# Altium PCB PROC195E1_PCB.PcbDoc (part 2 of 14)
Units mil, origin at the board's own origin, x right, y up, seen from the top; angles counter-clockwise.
Board outline 3110.24 x 2500 mil, 10 copper layers (Top Layer, L02_GND1, L03_SIG1, L04_GND2, L05_PWR1, L06_PWR2, L07_GND3, L08_SIG2, L09_GND4, Bottom Layer), stack 66.407 mil thick; 571 components, 538 nets, 6726 pads, 1286 vias.
Unrouted connection lines stored in the file: 4.
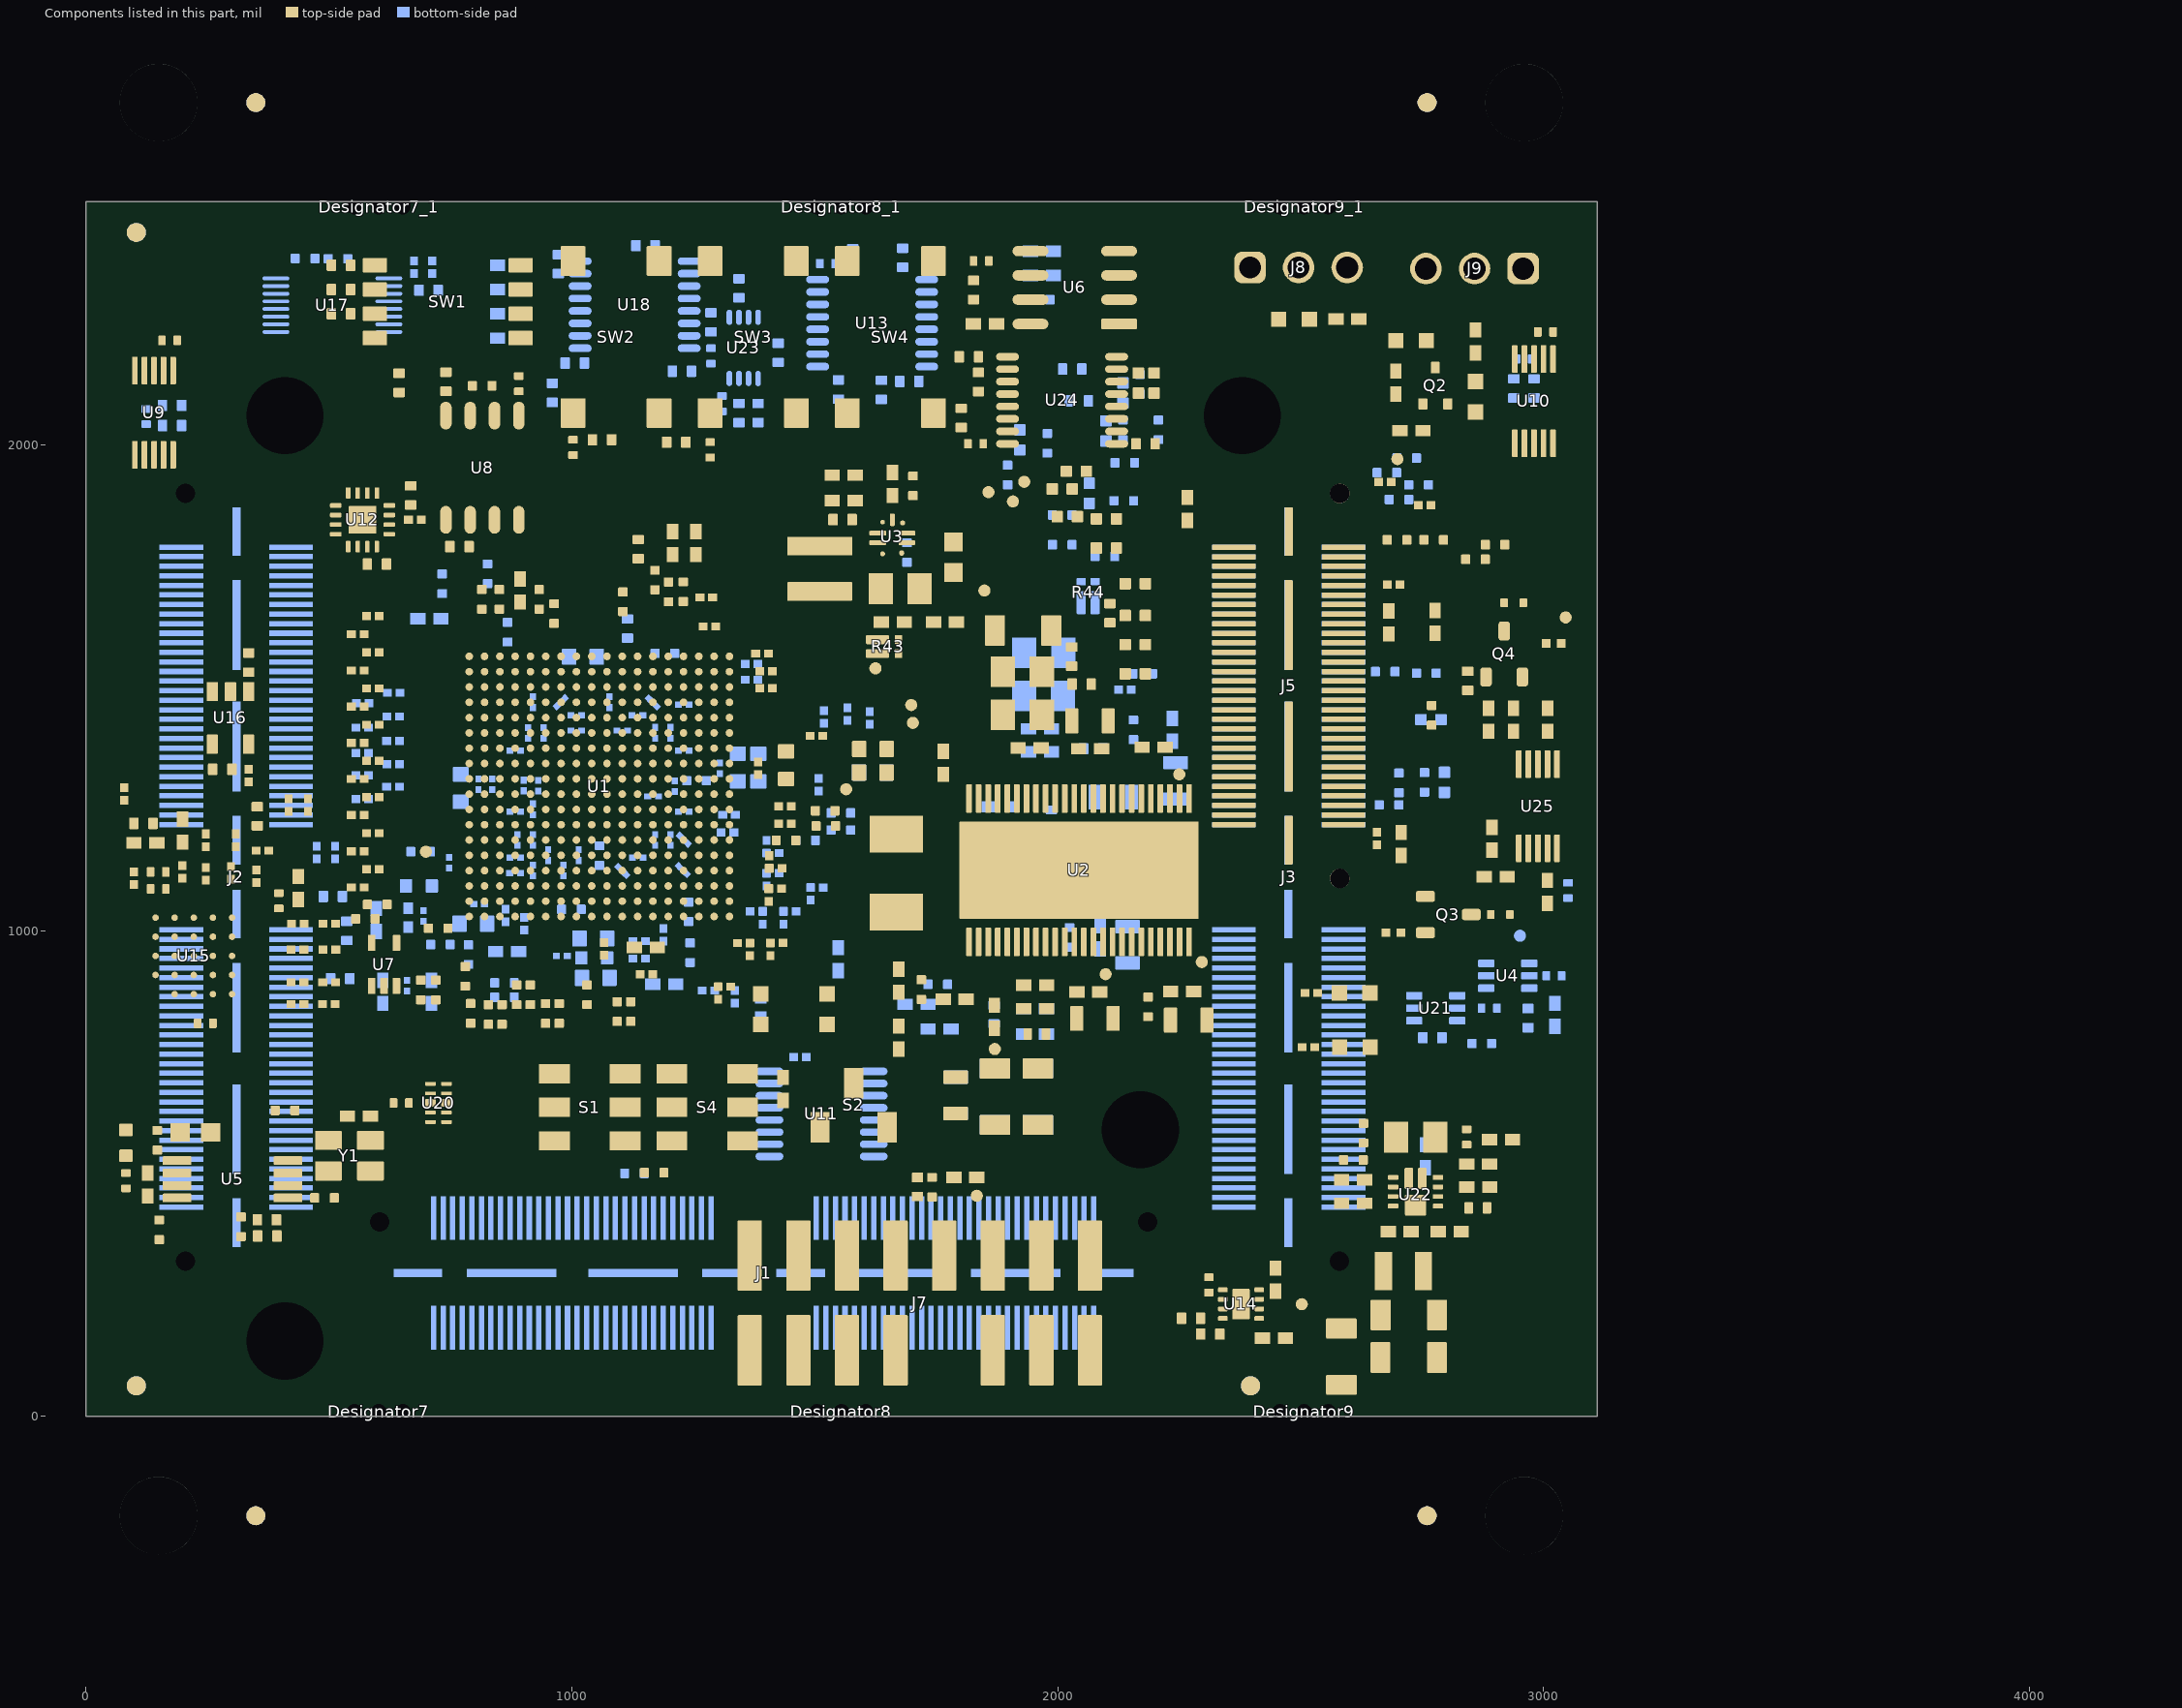
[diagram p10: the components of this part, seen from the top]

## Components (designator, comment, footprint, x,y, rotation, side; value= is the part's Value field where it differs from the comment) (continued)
R185 "RC0402JR-0710KL" FP-RC0402JR-0710KL_0402-MFG 508.58,1070.27 r0 bottom value=10k
R186 "RC0201FR-0722RL" 0201 350.94,1111.7 r90 top value=22.0
R187 "RC0201FR-0722RL" 0201 435.81,893.76 r0 top value=22.0
R188 "ERJ-2GE0R00X" FP-ERJ-2GE0R00X_0402-MFG 2608.6,527.84 r0 top value=0
R189 "RC0201FR-0722RL" 0201 199,1120.7 r90 top value=22.0
R190 "CRCW04021M05FKED" 0402 2756.8,535.51 r90 bottom value=1.05Meg
R191 "RC0201FR-0722RL" 0201 247.18,1116.75 r90 top value=22.0
R192 "CRCW040223K7FKED" 0402 2865.28,519.48 r180 top value=23.7k
R193 "RC0201FR-0722RL" 0201 298.96,1118.7 r90 top value=22.0
R194 "CRCW0402174KFKED" 0402 2607.99,487.06 r0 top value=174k
R195 "RC0201FR-0722RL" 0201 436.67,1013.96 r0 top value=22.0
R196 "RC0201FR-0722RL" 0201 435.81,960.62 r0 top value=22.0
R197 "RC0201FR-0722RL" 0201 435.81,848.86 r0 top value=22.0
R198 "RC0201FR-0722RL" 0201 99.13,1107.76 r90 top value=22.0
R199 "ERJ-1GN0R00C" 0201 79.05,1281.4 r90 top value=0
R200 "ERJ-2RKF1001X" 0402 122.75,1180.75 r180 top value=1.00k
R201 "CRCW0402100KJNED" 0402 597.6,1021.92 r90 bottom value=100k
R202 "CRCW04024K70JNED" 0402 1207.93,1797.45 r90 top value=4.7k
R203 "CRCW04024K70JNED" 0402 1255.29,1797.45 r90 top value=4.7k
R204 "ERJ-2GE0R00X" FP-ERJ-2GE0R00X_0402-MFG 826.74,1734.45 r270 bottom value=0
R205 "RC0402JR-0710KL" FP-RC0402JR-0710KL_0402-MFG 335.2,1551.63 r90 top value=10k
R206 "RC0402JR-0710KL" FP-RC0402JR-0710KL_0402-MFG 281.06,1332.07 r0 top value=10k
R207 "ERJ-2GE0R00X" FP-ERJ-2GE0R00X_0402-MFG 733.39,1713.85 r270 bottom value=0
R208 "ERJ-2GE0R00X" FP-ERJ-2GE0R00X_0402-MFG 933.1,1681.87 r270 top value=0
R209 "CRCW0402118KFKED" 0402 2865.56,472.3 r180 top value=118k
R210 "ERJ-2GE0R00X" FP-ERJ-2GE0R00X_0402-MFG 151.15,384.1 r270 top value=0
R211 "ERJ-2GE0R00X" FP-ERJ-2GE0R00X_0402-MFG 1105.33,1676.87 r270 top value=0
R212 "ERJ-2GE0R00X" FP-ERJ-2GE0R00X_0402-MFG 963.78,1652.65 r270 top value=0
R213 "ERJ-2GE0R00X" FP-ERJ-2GE0R00X_0402-MFG 147.24,568.51 r90 top value=0
R214 "ERJ-2GE0R00X" FP-ERJ-2GE0R00X_0402-MFG 1169.64,501.69 r180 top value=0
R215 "ERJ-2GE0R00X" FP-ERJ-2GE0R00X_0402-MFG 1129.23,500.3 r0 bottom value=0
R216 "CRCW0402100RFKED" 0402 2681.28,1634.07 r90 top value=100
R217 "ERJ-2GE0R00X" FP-ERJ-2GE0R00X_0402-MFG 1171.31,1721.49 r270 top value=0
R218 "ERJ-2RKF1001X" 0402 871.25,2369.54 r180 bottom value=1.00k
R219 "ERJ-2RKF1001X" 0402 871.25,2319.54 r180 bottom value=1.00k
R220 "ERJ-2RKF1001X" 0402 871.25,2269.54 r180 bottom value=1.00k
R221 "ERJ-2RKF1001X" 0402 871.25,2219.54 r180 bottom value=1.00k
R222 "RC0402JR-0710KL" FP-RC0402JR-0710KL_0402-MFG 705.41,2317.95 r0 bottom value=10k
R223 "RC0402JR-0710KL" FP-RC0402JR-0710KL_0402-MFG 352.91,1235.31 r90 top value=10k
R224 "RC0402JR-0710KL" FP-RC0402JR-0710KL_0402-MFG 523.69,901 r0 bottom value=10k
R225 "RC0402JR-0710KL" FP-RC0402JR-0710KL_0402-MFG 1136.94,1785.19 r90 top value=10k
R226 "RC0402JR-0710KL" FP-RC0402JR-0710KL_0402-MFG 1114.68,1621.77 r90 bottom value=10k
R227 "RC0402JR-0710KL" FP-RC0402JR-0710KL_0402-MFG 644.79,2127.36 r90 top value=10k
R228 "RC0402JR-0710KL" FP-RC0402JR-0710KL_0402-MFG 525.19,2269.54 r0 top value=10k
R229 "RC0402JR-0710KL" FP-RC0402JR-0710KL_0402-MFG 525.19,2319.54 r0 top value=10k
R230 "RC0402JR-0710KL" FP-RC0402JR-0710KL_0402-MFG 525.19,2369.54 r0 top value=10k
R231 "ERJ-2GE0R00X" FP-ERJ-2GE0R00X_0402-MFG 451.38,2383.37 r0 bottom value=0
R232 "ERJ-2GE0R00X" FP-ERJ-2GE0R00X_0402-MFG 519.14,2382.89 r180 bottom value=0
R233 "ERJ-2GEJ152X" FP-ERJ-2GEJ152X_0402-MFG 1553.88,1206.89 r180 bottom value=1.5k
R234 "ERJ-2GEJ152X" FP-ERJ-2GEJ152X_0402-MFG 1481.4,1185.59 r0 bottom value=1.5k
R235 "ERJ-2GE0R00X" FP-ERJ-2GE0R00X_0402-MFG 1441.05,1185.59 r180 top value=0
R236 "ERJ-2GE0R00X" FP-ERJ-2GE0R00X_0402-MFG 1553.88,1242.11 r180 bottom value=0
R237 "ERJ-2GE0R00X" FP-ERJ-2GE0R00X_0402-MFG 729.88,971.43 r0 bottom value=0
R238 "ERJ-1GN0R00C" 0201 1613.18,1437.62 r90 bottom value=0
R239 "ERJ-1GN0R00C" 0201 1335.6,863.52 r90 bottom value=0
R240 "ERJ-2GE0R00X" FP-ERJ-2GE0R00X_0402-MFG 946.13,829.5 r90 top value=0
R241 "ERJ-2GE0R00X" FP-ERJ-2GE0R00X_0402-MFG 974.13,829.5 r90 top value=0
R242 "ERJ-2GE0R00X" FP-ERJ-2GE0R00X_0402-MFG 861.61,862.81 r0 bottom value=0
R243 "ERJ-2GE0R00X" FP-ERJ-2GE0R00X_0402-MFG 861.61,892.26 r0 bottom value=0
R244 "ERJ-2GE0R00X" FP-ERJ-2GE0R00X_0402-MFG 1093.49,833.2 r90 top value=0
R245 "RC0402JR-0710KL" FP-RC0402JR-0710KL_0402-MFG 1062.42,2010.26 r180 top value=10k
R246 "RC0402JR-0710KL" FP-RC0402JR-0710KL_0402-MFG 2771.13,779.4 r0 bottom value=10k
R247 "ERJ-2GE0R00X" FP-ERJ-2GE0R00X_0402-MFG 2872.7,767.51 r180 bottom value=0
R248 "RC0402JR-0710KL" FP-RC0402JR-0710KL_0402-MFG 1344.16,2065.26 r90 bottom value=10k
R249 "CRCW04024K70JNED" 0402 3023.19,826.5 r90 bottom value=4.7k
R250 "RC0402JR-0710KL" FP-RC0402JR-0710KL_0402-MFG 1215.21,2005.26 r0 top value=10k
R251 "RC0402JR-0710KL" FP-RC0402JR-0710KL_0402-MFG 2968,819.85 r270 bottom value=10k
R252 "RC0402JR-0710KL" FP-RC0402JR-0710KL_0402-MFG 1826.89,2318.57 r90 top value=10k
R253 "RC0402JR-0710KL" FP-RC0402JR-0710KL_0402-MFG 1344.16,2322.1 r270 bottom value=10k
R254 "RC0402JR-0710KL" FP-RC0402JR-0710KL_0402-MFG 2043.54,2090.36 r0 bottom value=10k
R255 "RC0402JR-0710KL" FP-RC0402JR-0710KL_0402-MFG 2029.91,2155.79 r0 bottom value=10k
R256 "RC0402JR-0710KL" FP-RC0402JR-0710KL_0402-MFG 1817.2,2181.04 r0 top value=10k
R257 "RC0402JR-0710KL" FP-RC0402JR-0710KL_0402-MFG 1836.89,2129.2 r270 top value=10k
R258 "RC0402JR-0710KL" FP-RC0402JR-0710KL_0402-MFG 2180.98,2002.06 r0 top value=10k
R259 "RC0402JR-0710KL" FP-RC0402JR-0710KL_0402-MFG 1801.56,2055.24 r270 top value=10k
R260 "CRCW04024K70JNED" 0402 2706.82,1178.56 r270 top value=4.7k
R261 "ERJ-1GN0R00C" 0201 1393.15,1026.54 r90 bottom value=0
R262 "ERJ-1GN0R00C" 0201 1401.07,1172.66 r270 bottom value=0
R263 "ERJ-1GN0R00C" 0201 1414.06,1159.67 r180 bottom value=0
R264 "ERJ-1GN0R00C" 0201 1314.34,884.78 r0 top value=0
R265 "ERJ-2RKF1001X" 0402 2727.9,2028.96 r0 top value=1.00k
R266 "CRCW04024K70JNED" 0402 2886.74,1434.06 r90 top value=4.7k
R267 "CRCW04024K70JNED" 0402 2938.15,1433.98 r90 top value=4.7k
R268 "CRCW04024K70JNED" 0402 3008.15,1433.98 r90 top value=4.7k
R269 "ERJ-2RKF1001X" 0402 2893.51,1188.98 r270 top value=1.00k
R270 "ERJ-2RKF1001X" 0402 2901.38,1110.57 r180 top value=1.00k
R271 "AC0402FR-0710KL" 0402 3007.89,1079.84 r90 top value=10.0k
R272 "ERJ-2GE0R00X" FP-ERJ-2GE0R00X_0402-MFG 1121.49,833.2 r90 top value=0
R273 "ERJ-2GE0R00X" FP-ERJ-2GE0R00X_0402-MFG 914.72,867.87 r90 top value=0
R274 "ERJ-2GE0R00X" FP-ERJ-2GE0R00X_0402-MFG 886.72,867.87 r90 top value=0
R275 "ERJ-2GE0R00X" FP-ERJ-2GE0R00X_0402-MFG 828.55,827.38 r90 top value=0
R276 "ERJ-2GE0R00X" FP-ERJ-2GE0R00X_0402-MFG 856.55,827.38 r90 top value=0
R277 "ERJ-2GE0R00X" FP-ERJ-2GE0R00X_0402-MFG 781.1,905.79 r90 top value=0
R278 "ERJ-2GE0R00X" FP-ERJ-2GE0R00X_0402-MFG 791.99,829.72 r90 top value=0
R279 "ERJ-2GEJ221X" RESC1005X40X25LL05T05 2690.99,995.64 r180 top
R280 "ERJ-2GEJ221X" RESC1005X40X25LL05T05 3020.77,1591.21 r0 top
R281 "RC0402JR-0710KL" FP-RC0402JR-0710KL_0402-MFG 2843.82,1514.02 r270 top value=10k
R282 "ERJ-1GN0R00C" 0201 1469.89,739.87 r0 bottom value=0
R283 "ERJ-1GN0R00C" 0201 1301.35,871.79 r270 top value=0
R284 "ERJ-1GN0R00C" 0201 1421.89,974.55 r0 top value=0
R285 "ERJ-1GN0R00C" 0201 1408.9,961.55 r270 top value=0
R286 "ERJ-1GN0R00C" 0201 1353.81,974.18 r180 top value=0
R287 "ERJ-1GN0R00C" 0201 1366.8,961.19 r270 top value=0
R288 "ERJ-1GN0R00C" 0201 1448.66,1039.53 r0 bottom value=0
R289 "ERJ-1GN0R00C" 0201 1435.67,1026.54 r270 bottom value=0
R290 "ERJ-1GN0R00C" 0201 1401.07,1105.07 r270 bottom value=0
R291 "ERJ-1GN0R00C" 0201 1414.06,1118.06 r0 bottom value=0
R292 "ERJ-1GN0R00C" 0201 1405.5,1073.36 r270 top value=0
R293 "ERJ-1GN0R00C" 0201 1418.5,1086.35 r0 top value=0
R294 "ERJ-1GN0R00C" 0201 1406.47,1141.17 r90 top value=0
R295 "ERJ-1GN0R00C" 0201 1419.46,1128.18 r0 top value=0
R296 "ERJ-1GN0R00C" 0201 1491.61,1075.61 r270 bottom value=0
R297 "ERJ-1GN0R00C" 0201 1504.6,1088.61 r0 bottom value=0
R298 "RC0402JR-0710KL" FP-RC0402JR-0710KL_0402-MFG 1637.24,2113.04 r90 bottom value=10k
R299 "RC0402JR-0710KL" FP-RC0402JR-0710KL_0402-MFG 1694.75,2130.44 r180 bottom value=10k
R300 "RC0402JR-0710KL" FP-RC0402JR-0710KL_0402-MFG 1548.89,2113.57 r90 bottom value=10k
R301 "RC0402JR-0710KL" FP-RC0402JR-0710KL_0402-MFG 1424.91,2189.25 r90 bottom value=10k
R302 "RC0402JR-0710KL" FP-RC0402JR-0710KL_0402-MFG 1681.01,2384.85 r90 bottom value=10k
R303 "RC0402JR-0710KL" FP-RC0402JR-0710KL_0402-MFG 1578.39,2383.49 r90 bottom value=10k
R304 "RC0402JR-0710KL" FP-RC0402JR-0710KL_0402-MFG 960.1,2106.8 r90 bottom value=10k
R305 "RC0402JR-0710KL" FP-RC0402JR-0710KL_0402-MFG 1006.32,2168.12 r180 bottom value=10k
R306 "RC0402JR-0710KL" FP-RC0402JR-0710KL_0402-MFG 972.3,2371.88 r270 bottom value=10k
R307 "RC0402JR-0710KL" FP-RC0402JR-0710KL_0402-MFG 1151.82,2409.8 r0 bottom value=10k
R308 "RC0402JR-0710KL" FP-RC0402JR-0710KL_0402-MFG 1286.71,2252.02 r90 bottom value=10k
R309 "RC0402JR-0710KL" FP-RC0402JR-0710KL_0402-MFG 1226.82,2151.47 r0 bottom value=10k
R310 "ERJ-1GN0R00C" 0201 902.53,1013.91 r90 bottom value=0
R311 "ERJ-1GN0R00C" 0201 475.11,1160.36 r90 bottom value=0
R312 "ERJ-1GN0R00C" 0201 513.3,1160.36 r90 bottom value=0
R313 "ERJ-2GE0R00X" FP-ERJ-2GE0R00X_0402-MFG 2773.71,1804.15 r180 top value=0
R314 "ERJ-2GE0R00X" FP-ERJ-2GE0R00X_0402-MFG 2718.22,1972.55 r180 bottom value=0
R315 "ERJ-2GE0R00X" FP-ERJ-2GE0R00X_0402-MFG 2900.15,1794.32 r180 top value=0
R316 "ERJ-2GE0R00X" FP-ERJ-2GE0R00X_0402-MFG 2742.84,1917.46 r180 bottom value=0
S1 "CAS-D20TA" SW_CAS-D20TA 1037.26,636.32 r0 top
S2 "CAS-120TA" SW_CAS-120TA 1580.11,640.8 r90 top
S4 "CAS-D20TA" SW_CAS-D20TA 1278.67,636.33 r0 top
SW1 "416131160804" FP-416131160804_SMT_SW-MFG 744.87,2294.54 r270 top
SW2 "430182050816" FP-430182050816_SMT_SW_6MM2_6MM2-MFG 1091.32,2221.76 r270 top
SW3 "430182050816" FP-430182050816_SMT_SW_6MM2_6MM2-MFG 1373.48,2221.76 r270 top
SW4 "430182050816" FP-430182050816_SMT_SW_6MM2_6MM2-MFG 1655.65,2221.76 r90 top
TP1 "TESTPOINT" TP_25MIL-SMT 699.97,1162.37 r90 top
TP2 "TESTPOINT" TP_25MIL-SMT 2250.34,1321.58 r180 top
TP3 "TESTPOINT" TP_25MIL-SMT 2502.44,230.99 r90 top
TP4 "TESTPOINT" TP_25MIL-SMT 2699.22,1970.52 r90 top
TP5 "TESTPOINT" TP_25MIL-SMT 2296.51,935.35 r90 top
TP6 "TESTPOINT" TP_25MIL-SMT 1870.71,756.2 r90 top
TP7 "TESTPOINT" TP_25MIL-SMT 1833.72,454.17 r90 top
TP8 "TESTPOINT" TP_25MIL-SMT 1849.33,1700.02 r90 top
TP9 "TESTPOINT" TP_25MIL-SMT 2098.78,910.2 r0 top
TP10 "TESTPOINT" TP_25MIL-SMT 3045.37,1644.52 r90 top
TP11 "TESTPOINT" TP_25MIL-SMT 1931.18,1923.68 r0 top
TP12 "TESTPOINT" TP_25MIL-SMT 1907.87,1883.27 r270 top
TP13 "TESTPOINT" TP_25MIL-SMT 1702.27,1427.61 r90 top
TP14 "TESTPOINT" TP_25MIL-SMT 1857.69,1902.47 r180 top
TP15 "TESTPOINT" TP_25MIL-SMT 1698.58,1464.36 r180 top
TP16 "TESTPOINT" TP_25MIL-SMT 1625.09,1539.81 r0 top
TP17 "TESTPOINT" TP_25MIL-SMT 1564.79,1290.88 r90 top
TP18 "TESTPOINT" TP_25MIL-SMT 2951.32,989.35 r0 bottom
U1 "AM261x_ZCZ" ZCZ0324A-MFG 1056.88,1296.69 r0 top locked
U2 "TPS6538600QDCARQ1" DCA0048J-MFG 2044.02,1124.31 r90 top locked
U3 "TPS62903QRYTQ1" RYT0009A-MFG 1659.81,1808.16 r0 top
U4 "SN74LVC1G11DCKR" DCK0006A_N 2926.27,906.96 r0 bottom
U5 "LMK1C1104PWR" PW0008A-MFG 301.97,488.18 r180 top
U6 "CAT24M01WI-GT3" FP-CAT24M01WI-GT3_SOIC8-IPC_C 2035.19,2323.61 r180 top
U7 "SN74LV1T34DCKR" DCK0005A_N 613.98,930.43 r90 top
U8 "TMP411ADR" D0008A_N 816.14,1952.78 r270 top
U9 "INA228AIDGST" DGS0010A-MFG 140.51,2065.98 r90 top
U10 "INA228AIDGST" DGS0010A-MFG 2980.11,2089.59 r90 top
U11 "OPA4350EA/250" DBQ0016A_N 1514.17,622.68 r0 bottom
U12 "TCA6408ARGTR" RGT0016A 569.55,1845.49 r270 top
U13 "SN74CB3Q3257PWR" PW0016A_L 1618.37,2250.46 r180 bottom
U14 "TPS22965DSGT" DSG0008A-MFG 2377.36,231.18 r0 top
U15 "IS25LX256-LHLE" FP-IS25LX256-LHLE_TFBGA24-IPC_C 222.33,947.98 r90 top
U16 "SN74LVC1G08DBVR" DBV0005A_N 297.79,1437.81 r270 top
U17 "SN74AVC4T245DGVR" DGV0016A_N 507.56,2287.31 r180 bottom
U18 "SN74CB3Q3257PWR" PW0016A_L 1129.51,2288.22 r0 bottom
U20 "TMUX1136DQAR" DQA0010A 725.57,645.23 r180 top
U21 "SN74LVC1G11DCKR" DCK0006A_N 2777.91,840.27 r0 bottom
U22 "TPS61089RNRR" RNR0011A 2736.45,462.45 r180 top
U23 "SN74LVC3G17DCUR" DCU0008A_N 1354.01,2199.42 r270 bottom
U24 "SN74CB3Q3257PWR" PW0016A_L 2009.09,2091.63 r180 top
U25 "TMUX154EDGSR" DGS0010A-MFG 2988.2,1256.06 r270 top
Y1 "831055678" FP-831055678_SMT_OSC_3MM2_2MM5-MFG 542.64,536.65 r180 top
ZZ1 "This Assembly Note is for PCB labels only" ASSEMBLYNOTELABEL -337,3585 r0 top
ZZ2 "These assemblies are ESD sensitive, ESD precautions shall be observed." ASSEMBLYNOTE -346.3,3701.23 r0 top
ZZ3 "These assemblies must be clean and free from flux and all contaminants. Use of no clean flux is not acceptable." ASSEMBLYNOTE -347,3790 r0 top
ZZ4 "These assemblies must comply with workmanship standards IPC-A-610 Class 2, unless otherwise specified." ASSEMBLYNOTE -351,3896 r0 top

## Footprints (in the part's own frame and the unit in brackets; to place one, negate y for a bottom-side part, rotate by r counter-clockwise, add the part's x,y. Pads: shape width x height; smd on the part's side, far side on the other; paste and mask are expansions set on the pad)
0201 [mm] "Data from Kemet datasheet CC101_COM dated 7/28/11"
  rect 0.46x0.42 smd mask+0.048: 1(-0.33,0) 2(0.33,0)
  body extent -0.31,-0.16 0.31,0.16, height 0.26
0201L [mm] "Data from Kemet datasheet CC101_COM dated 7/28/11"
  rect 0.36x0.32 smd mask+0.048: 1(-0.28,0) 2(0.28,0)
  body extent -0.31,-0.16 0.31,0.16, height 0.26
0402 [mm] "0402 from SM-752 data"
  rect 0.8x0.6 smd: 1(-0.6,0) 2(0.6,0)
  silkscreen extent -1.22,-0.52 1.22,0.52, body extent -0.55,-0.3 0.55,0.3, height 0.6
0402L [mm] "0402 from SM-752 data"
  rect 0.6x0.5 smd: 1(-0.5,0) 2(0.5,0)
  body extent -0.55,-0.3 0.55,0.3, height 0.6
0603 [mm] "0603 from SM-752 data"
  rect 1x0.95 smd: 1(-0.8,0) 2(0.8,0)
  silkscreen extent -1.52,-0.69 1.52,0.69, body extent -0.87,-0.47 0.87,0.47, height 1
0805_HV [mil] "0805 with 30mil clearance between pads"
  rect 50x63 smd: 1(-40,0) 2(40,0)
  silkscreen extent -74,-40 74,40, body extent -43,-29 43,29, height 57
ASSEMBLYNOTE [mil] "Assembly Note"
ASSEMBLYNOTELABEL [mil] "Assembly Note for PCB Labels"
BRAKE_WAY_HOLES1X3 [mil]
  round 27 hole 32 unplated mask+5.5: ""(-50,49.37) ""(0,49.37) ""(50,49.37)
CE_MARK_5MM [mil] "Minimum text height for CE Mark"
  silkscreen extent -138,-99 138,99
CONN_QSH-060-01-L-D-A [mil] "SAMTEC"
  rect 11x90 smd: 1(-679.23,-112.41) 2(-679.23,113.19) 3(-659.55,-112.41) 4(-659.55,113.19) 5(-639.86,-112.41) 6(-639.86,113.19) 7(-620.18,-112.41) 8(-620.18,113.19) 9(-600.49,-112.41) 10(-600.49,113.19) 11(-580.81,-112.41) 12(-580.81,113.19) 13(-561.12,-112.41) 14(-561.12,113.19) 15(-541.44,-112.41) 16(-541.44,113.19) 17(-521.75,-112.41) 18(-521.75,113.19) 19(-502.07,-112.41) 20(-502.07,113.19) 21(-482.38,-112.41) 22(-482.38,113.19) 23(-462.7,-112.41) 24(-462.7,113.19) 25(-443.01,-112.41) 26(-443.01,113.19) 27(-423.33,-112.41) 28(-423.33,113.19) 29(-403.64,-112.41) 30(-403.64,113.19) 31(-383.96,-112.41) 32(-383.96,113.19) 33(-364.27,-112.41) 34(-364.27,113.19) 35(-344.59,-112.41) 36(-344.59,113.19) 37(-324.9,-112.41) 38(-324.9,113.19) 39(-305.22,-112.41) 40(-305.22,113.19) 41(-285.53,-112.41) 42(-285.53,113.19) 43(-265.85,-112.41) 44(-265.85,113.19) 45(-246.16,-112.41) 46(-246.16,113.19) 47(-226.48,-112.41) 48(-226.48,113.19) 49(-206.79,-112.41) 50(-206.79,113.19) 51(-187.11,-112.41) 52(-187.11,113.19) 53(-167.42,-112.41) 54(-167.42,113.19) 55(-147.74,-112.41) 56(-147.74,113.19) 57(-128.05,-112.41) 58(-128.05,113.19) 59(-108.37,-112.41) 60(-108.37,113.19) 61(108.29,-112.41) 62(108.29,113.19) 63(127.97,-112.41) 64(127.97,113.19) 65(147.66,-112.41) 66(147.66,113.19) 67(167.34,-112.41) 68(167.34,113.19) 69(187.03,-112.41) 70(187.03,113.19) 71(206.71,-112.41) 72(206.71,113.19) 73(226.4,-112.41) 74(226.4,113.19) 75(246.08,-112.41) 76(246.08,113.19) 77(265.77,-112.41) 78(265.77,113.19) 79(285.45,-112.41) 80(285.45,113.19) 81(305.14,-112.41) 82(305.14,113.19) 83(324.82,-112.41) 84(324.82,113.19) 85(344.51,-112.41) 86(344.51,113.19) 87(364.19,-112.41) 88(364.19,113.19) 89(383.88,-112.41) 90(383.88,113.19) 91(403.56,-112.41) 92(403.56,113.19) 93(423.25,-112.41) 94(423.25,113.19) 95(442.93,-112.41) 96(442.93,113.19) 97(462.62,-112.41) 98(462.62,113.19) 99(482.3,-112.41) 100(482.3,113.19) 101(501.99,-112.41) 102(501.99,113.19) 103(521.67,-112.41) 104(521.67,113.19) 105(541.36,-112.41) 106(541.36,113.19) 107(561.04,-112.41) 108(561.04,113.19) 109(580.73,-112.41) 110(580.73,113.19) 111(600.41,-112.41) 112(600.41,113.19) 113(620.1,-112.41) 114(620.1,113.19) 115(639.78,-112.41) 116(639.78,113.19) 117(659.47,-112.41) 118(659.47,113.19) 119(679.15,-112.41) 120(679.15,113.19)
  rect 100x16.93 smd: 121(-711.22,0) 124(-76.18,0) 125(76.18,0) 128(711.22,0)
  rect 185.04x16.93 smd: 122(-518.7,0) 123(-268.7,0) 126(268.7,0) 127(518.7,0)
  round 35 hole 40 unplated: MH1(-789.96,105.12) MH2(789.96,105.12)
  body extent -811,-143 814,142, height 128
D0008A_N [mm] "SOIC, 8-Leads, Body 4.9x3.9mm, Pitch 1.27mm, IPC Medium Density"
  oval 1.45x0.6 smd: 1(-2.725,1.905) 2(-2.725,0.635) 3(-2.725,-0.635) 4(-2.725,-1.905) 5(2.725,-1.905) 6(2.725,-0.635) 7(2.725,0.635) 8(2.725,1.905)
  silkscreen extent -3.3,-2.5 0.9,2.5, body extent -3,-2.45 3,2.45, height 1.63
DBQ0016A_N [mm] "SOP, 16-Leads, Body 4.9x3.9mm, Pitch 0.635mm, IPC Medium Density"
  oval 1.45x0.4 smd: 1(-2.725,2.222) 2(-2.725,1.587) 3(-2.725,0.953) 4(-2.725,0.318) 5(-2.725,-0.318) 6(-2.725,-0.953) 7(-2.725,-1.587) 8(-2.725,-2.222) 9(2.725,-2.223) 10(2.725,-1.587) 11(2.725,-0.953) 12(2.725,-0.318) 13(2.725,0.318) 14(2.725,0.953) 15(2.725,1.588) 16(2.725,2.222)
  silkscreen extent -3.35,-2.5 1.1,2.68, body extent -3.01,-2.45 3.01,2.45, height 1.63
DBV0005A_N [mm] "SOT23, 5-Leads, Body 2.9x1.6mm, Pitch 0.95mm, Lead Span 2.8mm, IPC Medium Density"
  rrect17% 1x0.6 smd: 1(-1.375,0.95) 2(-1.375,0) 3(-1.375,-0.95) 4(1.375,-0.95) 5(1.375,0.95)
  silkscreen extent -0.25,-1.55 0.25,1.55, body extent -1.42,-1.46 1.42,1.46, height 1.09
DCA0048J-MFG [mm]
  rrect33% 1.5x0.3 smd paste+0 mask+0: 1(-3.75,5.75) 2(-3.75,5.25) 3(-3.75,4.75) 4(-3.75,4.25) 5(-3.75,3.75) 6(-3.75,3.25) 7(-3.75,2.75) 8(-3.75,2.25) 9(-3.75,1.75) 10(-3.75,1.25) 11(-3.75,0.75) 12(-3.75,0.25) 13(-3.75,-0.25) 14(-3.75,-0.75) 15(-3.75,-1.25) 16(-3.75,-1.75) 17(-3.75,-2.25) 18(-3.75,-2.75) 19(-3.75,-3.25) 20(-3.75,-3.75) 21(-3.75,-4.25) 22(-3.75,-4.75) 23(-3.75,-5.25) 24(-3.75,-5.75) 25(3.75,-5.75) 26(3.75,-5.25) 27(3.75,-4.75) 28(3.75,-4.25) 29(3.75,-3.75) 30(3.75,-3.25) 31(3.75,-2.75) 32(3.75,-2.25) 33(3.75,-1.75) 34(3.75,-1.25) 35(3.75,-0.75) 36(3.75,-0.25) 37(3.75,0.25) 38(3.75,0.75) 39(3.75,1.25) 40(3.75,1.75) 41(3.75,2.25) 42(3.75,2.75) 43(3.75,3.25) 44(3.75,3.75) 45(3.75,4.25) 46(3.75,4.75) 47(3.75,5.25) 48(3.75,5.75)
  rrect2% 5.1x12.5 smd paste-1000 mask-1000: 49(0,0)
  silkscreen extent -5.2,-6.3 3.1,6.3, body extent -4.6,-6.55 4.6,6.55, height 0.25
DCK0005A_N [mm] "SOT353, 5-Leads, Body 2x1.3mm, Pitch 0.65mm, Lead Span 2.1mm, IPC Medium Density"
  rrect25% 0.85x0.4 smd: 1(-1.125,0.65) 2(-1.125,0) 3(-1.125,-0.65) 4(1.125,-0.65) 5(1.125,0.65)
  silkscreen extent -1.48,-1.03 0.55,1.1, body extent -1.14,-1 1.14,1, height 0.95
DCK0006A_N [mm] "SOT23, 6-Leads, Body 2x1.3mm, Pitch 0.65mm, Lead Span 2.1mm, IPC Medium Density"
  rrect25% 0.85x0.4 smd: 1(-1.125,0.65) 2(-1.125,0) 3(-1.125,-0.65) 4(1.125,-0.65) 5(1.125,0) 6(1.125,0.65)
  silkscreen extent -1.5,-1.09 0.51,1.09, body extent -1.14,-1 1.14,1, height 0.95
DCU0008A_N [mm] "TSSOP, 8-Leads, Body 2x2.3mm, Pitch 0.5mm, IPC Medium Density"
  oval 0.8x0.3 smd: 1(-1.6,0.75) 2(-1.6,0.25) 3(-1.6,-0.25) 4(-1.6,-0.75) 5(1.6,-0.75) 6(1.6,-0.25) 7(1.6,0.25) 8(1.6,0.75)
  silkscreen extent -1.05,-1.05 0.38,1.05, body extent -1.56,-1 1.56,1, height 0.9
DFE252012P [mm] "TOKO, Pad sizes increased as per request"
  rect 0.9x2 smd: 1(-1.05,0) 2(1.05,0)
  silkscreen extent -0.3,-1.2 0.3,1.2, body extent -1.35,-1.1 1.35,1.1, height 1.2
DGS0010A-MFG [mm]
  rrect33% 1.45x0.3 smd paste+0 mask+0: 1(-2.2,1) 2(-2.2,0.5) 3(-2.2,0) 4(-2.2,-0.5) 5(-2.2,-1) 6(2.2,-1) 7(2.2,-0.5) 8(2.2,0) 9(2.2,0.5) 10(2.2,1)
  silkscreen extent -3.6,-1.55 1.05,1.55, body extent -3.03,-1.8 3.03,1.8, height 0.25
DGV0016A_N [mm] "TSSOP, 16-Leads, Body 3.6x4.4mm, Pitch 0.4mm, IPC Medium Density"
  oval 1.4x0.2 smd: 1(-2.95,1.4) 2(-2.95,1) 3(-2.95,0.6) 4(-2.95,0.2) 5(-2.95,-0.2) 6(-2.95,-0.6) 7(-2.95,-1) 8(-2.95,-1.4) 9(2.95,-1.4) 10(2.95,-1) 11(2.95,-0.6) 12(2.95,-0.2) 13(2.95,0.2) 14(2.95,0.6) 15(2.95,1) 16(2.95,1.4)
  silkscreen extent -3.45,-1.85 1.85,1.85, body extent -3.21,-1.8 3.21,1.8, height 1.2
DQA0010A [mm] "SON, 10-Leads, Body 1x2.5mm, Pitch 0.5mm, TI Recommended"
  rrect50% 0.565x0.2 smd: 1(-0.417,1) 2(-0.417,0.5) 4(-0.418,-0.5) 5(-0.417,-1) 6(0.418,-1) 7(0.418,-0.5) 9(0.418,0.5) 10(0.417,1)
  rrect28% 0.565x0.36 on Top Paste: 3(-0.418,0) 8(0.418,0)
  rrect25% 0.565x0.4 smd paste-0.2: 3(-0.417,0) 8(0.418,0)
  silkscreen extent -0.67,-1.45 0.55,1.45, body extent -0.55,-1.3 0.55,1.3, height 0.56
DSG0008A-MFG [mm]
  rrect40% 0.5x0.25 smd paste+0 mask+0: 1(-0.95,0.75) 2(-0.95,0.25) 3(-0.95,-0.25) 4(-0.95,-0.75) 5(0.95,-0.75) 6(0.95,-0.25) 7(0.95,0.25) 8(0.95,0.75)
  rrect11% 0.9x1.6 smd paste-1000 mask+0: 9(0,0)
  silkscreen extent -1.31,1.4 1,1.99, body extent -1.3,-1.15 1.3,1.15, height 0.25
FCC_DISCLAIMER [mil]
FIDUCIAL10-20 [mm]
  round 1 smd mask+0.5: 1(0,0)
  Top Layer keep-out circle w1.178: c0,0 r0.5
Fiducial10-20 [mm]
  round 1 smd mask+0.5: 1(0,0)
  Top Layer keep-out circle w1.178: c0,0 r0.5
FP-150040RS73220_0402-MFG [mm]
  rrect25% 0.4x0.46 smd paste+0 mask+0: 1(-0.5,0) 2(0.5,0)
  silkscreen extent -1.38,-0.61 0.5,0.61, body extent -0.8,-0.4 0.8,0.4, height 0.25
FP-831055678_SMT_OSC_3MM2_2MM5-MFG [mm]
  rrect10% 1.4x1 smd paste+0 mask+0: 1(-1.1,-0.8) 2(1.1,-0.8) 3(1.1,0.8) 4(-1.1,0.8)
  silkscreen extent -2.48,-1.3 0,1.3, body extent -1.9,-1.4 1.9,1.4, height 0.25
FP-416131160804_SMT_SW-MFG [mm]
  rrect13% 0.76x1.27 smd paste+0 mask+0: 1(-1.905,-3.81) 2(-0.635,-3.81) 3(0.635,-3.81) 4(1.905,-3.81) 5(1.905,3.81) 6(0.635,3.81) 7(-0.635,3.81) 8(-1.905,3.81)
  silkscreen extent -3.27,-3.94 3.28,2.93, body extent -3.37,-4.55 3.38,4.54, height 0.25
FP-430182050816_SMT_SW_6MM2_6MM2-MFG [mm]
  rrect8% 1.55x1.3 smd paste+0 mask+0: 1(-3.975,2.25) 2(-3.975,-2.25) 3(3.975,2.25) 4(3.975,-2.25)
  silkscreen extent -5.42,-3.2 3.2,3.2, body extent -4.85,-3.3 4.85,3.3, height 0.25
FP-BLM18EG101TN1D_0603-MFG [mm]
  rrect15% 0.65x0.7 smd paste+0 mask+0: 1(-0.675,0) 2(0.675,0)
  silkscreen extent -0.87,-0.75 0.88,0.75, body extent -0.8,-0.4 0.8,0.4, height 0.65
FP-BLM18EG121SN1D_0603-MFG [mm]
  rrect15% 0.65x0.7 smd paste+0 mask+0: 1(-0.675,0) 2(0.675,0)
  body extent -0.8,-0.4 0.8,0.4, height 0.95
FP-CAT24M01WI-GT3_SOIC8-IPC_C [mil]
  rrect18% 73.78x21.39 smd paste+0 mask+0: 1(-91.18,75)
  rrect100% 73.78x21.39 smd paste+0 mask+0: 2(-91.18,25) 3(-91.18,-25) 4(-91.18,-75) 5(91.18,-75) 6(91.18,-25) 7(91.18,25) 8(91.18,75)
  silkscreen extent -101,-96 35,106, body extent -132,-100 132,100, height 10
FP-CL10A335KP8NNNC_0603-MFG [mm]
  rrect13% 0.76x0.85 smd paste+0 mask+0: 1(-0.72,0) 2(0.72,0)
  silkscreen extent -0.85,0.8 0.85,0.8, body extent -0.8,-0.4 0.8,0.4, height 0.9
FP-ERJ-2GE0R00X_0402-MFG [mm]
  rrect21% 0.475x0.5 smd paste+0 mask+0: 1(-0.513,0) 2(0.513,0)
  silkscreen extent -0.53,-0.63 0.53,-0.63, body extent -0.5,-0.25 0.5,0.25, height 0.4
FP-ERJ-2GEJ152X_0402-MFG [mm]
  rrect21% 0.475x0.5 smd paste+0 mask+0: 1(-0.513,0) 2(0.513,0)
  silkscreen extent -0.53,-0.63 0.53,-0.63, body extent -0.85,-0.38 0.85,0.38, height 0.25
FP-ERJ-2GEJ330X_0402-MFG [mm]
  rrect21% 0.475x0.5 smd paste+0 mask+0: 1(-0.512,0) 2(0.513,0)
  body extent -0.85,-0.38 0.85,0.38, height 0.25
FP-FC4L16R010FER_0306-MFG [mm]
  rrect25% 0.475x0.4 smd paste+0 mask+0: 1(-0.363,0.75) 2(0.363,0.75)
  rrect21% 0.475x1.2 smd paste+0 mask+0: 3(-0.363,-0.35) 4(0.363,-0.35)
  silkscreen extent -0.5,-1.33 0.5,1.86, body extent -0.4,-0.8 0.4,0.8, height 0.7
FP-GJM1555C1H470JB01D_0402-MFG [mm]
  rrect25% 0.4x0.5 smd paste+0 mask+0: 1(-0.4,0) 2(0.4,0)
  silkscreen extent -0.53,-0.63 0.53,-0.63, body extent -0.7,-0.38 0.7,0.38, height 0.25
FP-GRM21BR61H106KE43L_0805-MFG [mm]
  rrect14% 0.7x1.3 smd paste+0 mask+0: 1(-0.95,0) 2(0.95,0)
  silkscreen extent -0.23,-0.72 0.23,0.72, body extent -1.4,-0.82 1.4,0.82, height 0.25
FP-GRM31CR61E476ME44K_1206-MFG [mm]
  rrect10% 1.05x1.6 smd paste+0 mask+0: 1(-1.475,0) 2(1.475,0)
  silkscreen extent -0.58,-0.9 0.58,0.9, body extent -2.1,-1 2.1,1, height 0.25
FP-GRM155C81E105KE11D_0402-MFG [mm]
  rrect25% 0.4x0.5 smd paste+0 mask+0: 1(-0.4,0) 2(0.4,0)
  silkscreen extent -0.52,0.65 0.53,0.65, body extent -0.7,-0.38 0.7,0.38, height 0.25
FP-GRM155R61A106ME18D_0402-MFG [mm]
  rrect22% 0.45x0.6 smd paste+0 mask+0: 1(-0.475,0) 2(0.475,0)
  silkscreen extent -0.6,0.65 0.6,0.65, body extent -0.8,-0.45 0.8,0.45, height 0.25
"FP-GRM155R61E225KE11D_0402 (1005 metric)-MFG" [mm]
  rrect22% 0.45x0.6 smd paste+0 mask+0: 1(-0.475,0) 2(0.475,0)
  silkscreen extent -0.6,-0.64 0.6,0.65, body extent -0.8,-0.45 0.8,0.45, height 0.25
FP-GRM155R71H104KE14D_0402-MFG [mm]
  rrect25% 0.4x0.5 smd paste+0 mask+0: 1(-0.4,0) 2(0.4,0)
  body extent -0.5,-0.25 0.5,0.25, height 0.55
FP-IS25LX256-LHLE_TFBGA24-IPC_C [mm]
  round 0.34 smd paste+0 mask+0: A2(-1,2) A3(0,2) A4(1,2) A5(2,2) B1(-2,1) B2(-1,1) B3(0,1) B4(1,1) B5(2,1) C1(-2,0) C2(-1,0) C3(0,0) C4(1,0) C5(2,0) D1(-2,-1) D2(-1,-1) D3(0,-1) D4(1,-1) D5(2,-1) E1(-2,-2) E2(-1,-2) E3(0,-2) E4(1,-2) E5(2,-2)
  silkscreen extent -3.62,-4 3,4, body extent -3.1,-4.1 3.1,4.1, height 0.25
FP-QSH-030-01-L-D-A_CONN_60-MFG [mm]
  rrect36% 0.279x2.27 smd paste+0 mask+0: 1(-7.25,-2.865) 2(-7.25,2.865) 3(-6.75,-2.865) 4(-6.75,2.865) 5(-6.25,-2.865) 6(-6.25,2.865) 7(-5.75,-2.865) 8(-5.75,2.865) 9(-5.25,-2.865) 10(-5.25,2.865) 11(-4.75,-2.865) 12(-4.75,2.865) 13(-4.25,-2.865) 14(-4.25,2.865) 15(-3.75,-2.865) 16(-3.75,2.865) 17(-3.25,-2.865) 18(-3.25,2.865) 19(-2.75,-2.865) 20(-2.75,2.865) 21(-2.25,-2.865) 22(-2.25,2.865) 23(-1.75,-2.865) 24(-1.75,2.865) 25(-1.25,-2.865) 26(-1.25,2.865) 27(-0.75,-2.865) 28(-0.75,2.865) 29(-0.25,-2.865) 30(-0.25,2.865) 31(0.25,-2.865) 32(0.25,2.865) 33(0.75,-2.865) 34(0.75,2.865) 35(1.25,-2.865) 36(1.25,2.865) 37(1.75,-2.865) 38(1.75,2.865) 39(2.25,-2.865) 40(2.25,2.865) 41(2.75,-2.865) 42(2.75,2.865) 43(3.25,-2.865) 44(3.25,2.865) 45(3.75,-2.865) 46(3.75,2.865) 47(4.25,-2.865) 48(4.25,2.865) 49(4.75,-2.865) 50(4.75,2.865) 51(5.25,-2.865) 52(5.25,2.865) 53(5.75,-2.865) 54(5.75,2.865) 55(6.25,-2.865) 56(6.25,2.865) 57(6.75,-2.865) 58(6.75,2.865) 59(7.25,-2.865) 60(7.25,2.865)
  rrect23% 2.54x0.43 smd paste+0 mask+0: P1(-8.065,0) P4(8.065,0)
  rrect23% 4.7x0.43 smd paste+0 mask+0: P2(-3.175,0) P3(3.175,0)
  round 1.02 hole 1.02 unplated paste-1000 mask+0: ""(-10.065,2.67) ""(10.065,2.67)
  silkscreen extent -10.72,-4.83 10.72,3.68, body extent -10.82,-4.1 10.82,4.1, height 0.25
FP-RC0402FR-0710RL_0402-MFG [mm]
  rrect20% 0.5x0.6 smd paste+0 mask+0: 1(-0.5,0) 2(0.5,0)
  silkscreen extent -0.5,-0.68 0.5,-0.68, body extent -0.5,-0.25 0.5,0.25, height 0.4
FP-RC0402JR-0710KL_0402-MFG [mm]
  rrect20% 0.5x0.6 smd paste+0 mask+0: 1(-0.5,0) 2(0.5,0)
  silkscreen extent -0.5,0.67 0.5,0.67, body extent -0.85,-0.4 0.85,0.4, height 0.25
FP-RCC040210R0FKED_0402-MFG [mm]
  rrect17% 0.6x0.6 smd paste+0 mask+0: 1(-0.525,0) 2(0.525,0)
  silkscreen extent -0.53,-0.67 0.53,0.67, body extent -0.92,-0.4 0.92,0.4, height 0.25
FP-TSM-108-01-L-DV-008-P-TR_HDR15-MFG [mm]
  rrect8% 1.27x3.68 smd paste+0 mask+0: 1(-8.89,-2.475) 2(-8.89,2.475) 3(-6.35,-2.475) 4(-6.35,2.475) 5(-3.81,-2.475) 6(-3.81,2.475) 7(-1.27,-2.475) 9(1.27,-2.475) 10(1.27,2.475) 11(3.81,-2.475) 12(3.81,2.475) 13(6.35,-2.475) 14(6.35,2.475) 15(8.89,-2.475) 16(8.89,2.475)
  silkscreen extent -10.16,-5 10.16,2.61, body extent -10.26,-4.41 10.26,4.42, height 0.25
FP-XGL4030-102MEC_SMD_IND_4MM0_4MM0-MFG [mm]
  rrect10% 0.98x3.4 smd paste+0 mask+0: 1(-1.185,0) 2(1.185,0)
  silkscreen extent -2.15,-2.15 2.15,2.15, body extent -2,-2 2,2, height 3.1
IHLP-2020BZ [mm] "Vishay Dale recommended land pattern.  Document 34261 rev 12-Sept-13"
  rect 1.915x2.79 smd: 1(-2.037,0) 2(2.037,0)
  silkscreen extent -2.9,-2.7 2.9,2.7, body extent -2.87,-2.72 2.87,2.72, height 2
MTG_159mil [mil] "159mil Non Plated Hole"
  round 150 hole 159 unplated: 1(0,0)
PW0008A-MFG [mm]
  rrect22% 1.5x0.45 smd paste+0 mask+0: 1(-2.9,0.975) 2(-2.9,0.325) 3(-2.9,-0.325) 4(-2.9,-0.975) 5(2.9,-0.975) 6(2.9,-0.325) 7(2.9,0.325) 8(2.9,0.975)
  silkscreen extent -3.22,-1.55 1.77,1.64, body extent -3.75,-1.8 3.75,1.8, height 0.25
PW0016A_L [mm] "TSOP, 16-Leads, Body 5x4.4mm, Pitch 0.65mm, IPC High Density"
  oval 1.2x0.4 smd: 1(-2.85,2.275) 2(-2.85,1.625) 3(-2.85,0.975) 4(-2.85,0.325) 5(-2.85,-0.325) 6(-2.85,-0.975) 7(-2.85,-1.625) 8(-2.85,-2.275) 9(2.85,-2.275) 10(2.85,-1.625) 11(2.85,-0.975) 12(2.85,-0.325) 13(2.85,0.325) 14(2.85,0.975) 15(2.85,1.625) 16(2.85,2.275)
  silkscreen extent -2,-2.55 1.85,2.55, body extent -3.21,-2.5 3.21,2.5, height 1
RESC1005X40X25LL05T05 [mm] "Chip Resistor, 2-Leads, Body 1.05x0.55mm, IPC High Density"
  rect 0.45x0.45 smd: 1(-0.4,0) 2(0.4,0)
  body extent -0.53,-0.28 0.53,0.28, height 0.4
RGT0016A [mm] "QFN, 16-Leads, Body 3x3mm, Pitch 0.5mm, Thermal Pad 1.45x1.45mm, TI Recommended"
  rrect42% 0.6x0.24 smd: 1(-1.4,0.75) 2(-1.4,0.25) 3(-1.4,-0.25) 4(-1.4,-0.75) 9(1.4,-0.75) 10(1.4,-0.25) 11(1.4,0.25) 12(1.4,0.75)
  rrect42% 0.24x0.6 smd: 5(-0.75,-1.4) 6(-0.25,-1.4) 7(0.25,-1.4) 8(0.75,-1.4) 13(0.75,1.4) 14(0.25,1.4) 15(-0.25,1.4) 16(-0.75,1.4)
  rrect7% 1.34x1.34 on Top Paste: 17(0,0)
  rrect7% 1.45x1.45 smd paste-0.725: 17(0,0)
  silkscreen extent -1.73,-1.73 1.73,1.72, body extent -1.5,-1.5 1.5,1.5, height 1
RNR0011A [mm]
  rrect40% 0.25x0.6 on Top Solder: 0(-0.375,0.9) 0(0.375,0.9)
  rrect40% 0.25x0.28 on Top Paste: 0(-0.375,1.06) 0(0.375,1.06)
  rrect29% 0.35x0.92 on Top Paste: 0(-0.35,-0.74) 0(0.35,-0.74)
  rrect19% 1x0.52 on Top Solder: 0(0,0.46)
  rrect19% 1x0.52 on Top Paste: 0(0,0.46)
  rrect40% 0.55x0.25 smd: 1(-1.175,0.75) 2(-1.175,0.25) 3(-1.175,-0.25) 4(-1.175,-0.75) 7(1.175,-0.75) 8(1.175,-0.25) 9(1.175,0.25) 10(1.175,0.75)
  rrect29% 0.45x1.1 smd paste-0.225 mask-0.05: 5(-0.35,-0.7) 6(0.35,-0.7)
  rrect10% 1.1x1.1 smd paste-0.6 mask-0.6: 11(0,0.7)
  silkscreen extent -1.38,-1.15 1.38,1.15, body extent -1.3,-1.05 1.3,1.05, height 1.01
RYT0009A-MFG [mm]
  rrect40% 0.875x0.25 smd paste+0 mask+0: 1(-0.763,0.25) 2(-0.763,-0.25) 5(0.763,-0.25) 6(0.763,0.25)
  round 0.255 smd paste+0 mask+0: 3(-0.509,-0.828)
  round 0.278 smd paste+0 mask+0: 4(0.488,-0.787)
  round 0.26 smd paste+0 mask+0: 7(0.537,0.787)
  rrect40% 0.25x0.65 smd paste+0 mask+0: 8(0,0.95)
  round 0.242 smd paste+0 mask+0: 9(-0.509,0.828)
  Top Layer region: 1.2,0.825 1.193,0.85 1.175,0.868 1.15,0.875 1.15,0.875 0.675,0.875 0.656,0.879 0.64,0.89 0.629,0.906 0.625,0.925 0.625,0.925 0.625,1.225 0.618,1.25 0.6,1.268 0.575,1.275 0.575,1.275 0.425,1.275 0.406,1.271 0.39,1.26 0.379,1.244 0.375,1.225 0.375,1.225 0.375,0.675 0.379,0.656 0.39,0.64 0.406,0.629 0.425,0.625 0.425,0.625 1.15,0.625 1.169,0.629 1.185,0.64 1.196,0.656 1.2,0.675 1.2,0.675
  Top Layer region: -1.2,0.825 -1.193,0.85 -1.175,0.868 -1.15,0.875 -1.15,0.875 -0.675,0.875 -0.656,0.879 -0.64,0.89 -0.629,0.906 -0.625,0.925 -0.625,0.925 -0.625,1.225 -0.618,1.25 -0.6,1.268 -0.575,1.275 -0.575,1.275 -0.425,1.275 -0.406,1.271 -0.39,1.26 -0.379,1.244 -0.375,1.225 -0.375,1.225 -0.375,0.675 -0.379,0.656 -0.39,0.64 -0.406,0.629 -0.425,0.625 -0.425,0.625 -1.15,0.625 -1.169,0.629 -1.185,0.64 -1.196,0.656 -1.2,0.675 -1.2,0.675
  Top Layer region: 1.2,-0.825 1.193,-0.85 1.175,-0.868 1.15,-0.875 1.15,-0.875 0.675,-0.875 0.656,-0.879 0.64,-0.89 0.629,-0.906 0.625,-0.925 0.625,-0.925 0.625,-1.225 0.618,-1.25 0.6,-1.268 0.575,-1.275 0.575,-1.275 0.425,-1.275 0.406,-1.271 0.39,-1.26 0.379,-1.244 0.375,-1.225 0.375,-1.225 0.375,-0.912 0.372,-0.894 0.363,-0.879 0.35,-0.868 0.35,-0.868 0.337,-0.857 0.328,-0.842 0.325,-0.825 0.325,-0.825 0.325,-0.675 0.329,-0.656 0.34,-0.64 0.356,-0.629 0.375,-0.625 0.375,-0.625 1.15,-0.625 1.169,-0.629 1.185,-0.64 1.196,-0.656 1.2,-0.675 1.2,-0.675
  Top Layer region: -1.2,-0.825 -1.193,-0.85 -1.175,-0.868 -1.15,-0.875 -1.15,-0.875 -0.675,-0.875 -0.656,-0.879 -0.64,-0.89 -0.629,-0.906 -0.625,-0.925 -0.625,-0.925 -0.625,-1.225 -0.618,-1.25 -0.6,-1.268 -0.575,-1.275 -0.575,-1.275 -0.425,-1.275 -0.406,-1.271 -0.39,-1.26 -0.379,-1.244 -0.375,-1.225 -0.375,-1.225 -0.375,-0.912 -0.368,-0.887 -0.35,-0.868 -0.35,-0.868 -0.337,-0.857 -0.328,-0.842 -0.325,-0.825 -0.325,-0.825 -0.325,-0.675 -0.329,-0.656 -0.34,-0.64 -0.356,-0.629 -0.375,-0.625 -0.375,-0.625 -1.15,-0.625 -1.169,-0.629 -1.185,-0.64 -1.196,-0.656 -1.2,-0.675 -1.2,-0.675
  silkscreen extent -1.46,-1.68 1.05,0.32, body extent -1.3,-1.38 1.3,1.38, height 0.25
SOT-23 [mm] "SOT23, 3-Leads, Body 2.9x1.3mm, Pitch 0.95mm, Lead Span 2.5mm, IPC Medium Density"
  rrect50% 1x0.6 smd: 1(-1.2,0.95) 2(-1.2,-0.95) 3(1.2,0)
  silkscreen extent -1.63,-1.5 0.7,1.5, body extent -1.16,-1.45 1.21,1.45, height 1
SOT-323 [mm] "Diodes Inc recommended land pattern.  2016-02-24"
  rrect21% 0.6x0.47 smd: 1(-0.95,0.65) 2(-0.95,-0.65) 3(0.95,0)
  silkscreen extent -1.14,-1.22 0.77,1.22, body extent -1.13,-1.13 1.12,1.12, height 1.13
SW_CAS-120TA [mm] "COPAL ELECTRONICS"
  rect 1.6x1 smd: 1(-1.15,1.75) 2(1.15,0) 3(-1.15,-1.75)
  silkscreen extent -2,-2.85 1.4,2.93, body extent -1.4,-2.85 1.4,2.85, height 2.51
SW_CAS-D20TA [mm] "SMD, 6-Leads, Body 5.4x3.9mm, Pitch 1.75mm"
  rect 1.6x1 smd: 1(-1.85,1.75) 2(-1.85,0) 3(-1.85,-1.75) 4(1.85,1.75) 5(1.85,0) 6(1.85,-1.75)
  silkscreen extent -1.95,-2.7 1.95,2.9, body extent -2.1,-2.7 2.1,2.7, height 2.5
TI_STACKED_OVERLAY_SMALL [mil]
  silkscreen extent -418,-98 418,98
TP_25MIL-SMT [mil]
  round 25 smd mask-2.5: 1(0,0)
WEEE_Minimum [mil] "WEEElie bin"
  silkscreen extent -95,-172 99,104
WL-SMCW_GREEN [mm] "WURTH"
  rect 0.8x0.8 smd: 1(-0.8,0) 2(0.8,0)
  silkscreen extent -1.9,-0.8 1.2,0.8, body extent -0.85,-0.45 0.85,0.45, height 0.8
WURTH_61300311121 [mm] "Header, 2.54mm, 3x1, TH"
  rrect50% 1.65x1.65 hole 1.15: 1(-2.54,0)
  round 1.65 hole 1.15: 2(0,0) 3(2.54,0)
  body extent -3.81,-1.27 3.81,1.27, height 8.54
ZCZ0324A-MFG [mm]
  round 0.4 smd paste+0 mask+0.05: A1(-6.8,6.8) A2(-6,6.8) A3(-5.2,6.8) A4(-4.4,6.8) A5(-3.6,6.8) A6(-2.8,6.8) A7(-2,6.8) A8(-1.2,6.8) A9(-0.4,6.8) A10(0.4,6.8) A11(1.2,6.8) A12(2,6.8) A13(2.8,6.8) A14(3.6,6.8) A15(4.4,6.8) A16(5.2,6.8) A17(6,6.8) A18(6.8,6.8) B1(-6.8,6) B2(-6,6) B3(-5.2,6) B4(-4.4,6) B5(-3.6,6) B6(-2.8,6) B7(-2,6) B8(-1.2,6) B9(-0.4,6) B10(0.4,6) B11(1.2,6) B12(2,6) B13(2.8,6) B14(3.6,6) B15(4.4,6) B16(5.2,6) B17(6,6) B18(6.8,6) C1(-6.8,5.2) C2(-6,5.2) C3(-5.2,5.2) C4(-4.4,5.2) C5(-3.6,5.2) C6(-2.8,5.2) C7(-2,5.2) C8(-1.2,5.2) C9(-0.4,5.2) C10(0.4,5.2) C11(1.2,5.2) C12(2,5.2) C13(2.8,5.2) C14(3.6,5.2) C15(4.4,5.2) C16(5.2,5.2) C17(6,5.2) C18(6.8,5.2) D1(-6.8,4.4) D2(-6,4.4) D3(-5.2,4.4) D4(-4.4,4.4) D5(-3.6,4.4) D6(-2.8,4.4) D7(-2,4.4) D8(-1.2,4.4) D9(-0.4,4.4) D10(0.4,4.4) D11(1.2,4.4) D12(2,4.4) D13(2.8,4.4) D14(3.6,4.4) D15(4.4,4.4) D16(5.2,4.4) D17(6,4.4) D18(6.8,4.4) E1(-6.8,3.6) E2(-6,3.6) E3(-5.2,3.6) E4(-4.4,3.6) E5(-3.6,3.6) E6(-2.8,3.6) E7(-2,3.6) E8(-1.2,3.6) E9(-0.4,3.6) E10(0.4,3.6) E11(1.2,3.6) E12(2,3.6) E13(2.8,3.6) E14(3.6,3.6) E15(4.4,3.6) E16(5.2,3.6) E17(6,3.6) E18(6.8,3.6) F1(-6.8,2.8) F2(-6,2.8) F3(-5.2,2.8) F4(-4.4,2.8) F5(-3.6,2.8) F6(-2.8,2.8) F7(-2,2.8) F8(-1.2,2.8) F9(-0.4,2.8) F10(0.4,2.8) F11(1.2,2.8) F12(2,2.8) F13(2.8,2.8) F14(3.6,2.8) F15(4.4,2.8) F16(5.2,2.8) F17(6,2.8) F18(6.8,2.8) G1(-6.8,2) G2(-6,2) G3(-5.2,2) G4(-4.4,2) G5(-3.6,2) G6(-2.8,2) G7(-2,2) G8(-1.2,2) G9(-0.4,2) G10(0.4,2) G11(1.2,2) G12(2,2) G13(2.8,2) G14(3.6,2) G15(4.4,2) G16(5.2,2) G17(6,2) G18(6.8,2) H1(-6.8,1.2) H2(-6,1.2) H3(-5.2,1.2) H4(-4.4,1.2) H5(-3.6,1.2) H6(-2.8,1.2) H7(-2,1.2) H8(-1.2,1.2) H9(-0.4,1.2) H10(0.4,1.2) H11(1.2,1.2) H12(2,1.2) H13(2.8,1.2) H14(3.6,1.2) H15(4.4,1.2) H16(5.2,1.2) H17(6,1.2) H18(6.8,1.2) J1(-6.8,0.4) J2(-6,0.4) J3(-5.2,0.4) J4(-4.4,0.4) J5(-3.6,0.4) J6(-2.8,0.4) J7(-2,0.4) J8(-1.2,0.4) J9(-0.4,0.4) J10(0.4,0.4) J11(1.2,0.4) J12(2,0.4) J13(2.8,0.4) J14(3.6,0.4) J15(4.4,0.4) J16(5.2,0.4) J17(6,0.4) J18(6.8,0.4) K1(-6.8,-0.4) K2(-6,-0.4) K3(-5.2,-0.4) K4(-4.4,-0.4) K5(-3.6,-0.4) K6(-2.8,-0.4) K7(-2,-0.4) K8(-1.2,-0.4) K9(-0.4,-0.4) K10(0.4,-0.4) K11(1.2,-0.4) K12(2,-0.4) K13(2.8,-0.4) K14(3.6,-0.4) K15(4.4,-0.4) K16(5.2,-0.4) K17(6,-0.4) K18(6.8,-0.4) L1(-6.8,-1.2) L2(-6,-1.2) L3(-5.2,-1.2) L4(-4.4,-1.2) L5(-3.6,-1.2) L6(-2.8,-1.2) L7(-2,-1.2) L8(-1.2,-1.2) L9(-0.4,-1.2) L10(0.4,-1.2) L11(1.2,-1.2) L12(2,-1.2) L13(2.8,-1.2) L14(3.6,-1.2) L15(4.4,-1.2) L16(5.2,-1.2) L17(6,-1.2) L18(6.8,-1.2) M1(-6.8,-2) M2(-6,-2) M3(-5.2,-2) M4(-4.4,-2) M5(-3.6,-2) M6(-2.8,-2) M7(-2,-2) M8(-1.2,-2) M9(-0.4,-2) M10(0.4,-2) M11(1.2,-2) M12(2,-2) M13(2.8,-2) M14(3.6,-2) M15(4.4,-2) M16(5.2,-2) M17(6,-2) M18(6.8,-2) N1(-6.8,-2.8) N2(-6,-2.8) N3(-5.2,-2.8) N4(-4.4,-2.8) N5(-3.6,-2.8) N6(-2.8,-2.8) N7(-2,-2.8) N8(-1.2,-2.8) N9(-0.4,-2.8) N10(0.4,-2.8) N11(1.2,-2.8) N12(2,-2.8) N13(2.8,-2.8) N14(3.6,-2.8) N15(4.4,-2.8) N16(5.2,-2.8) N17(6,-2.8) N18(6.8,-2.8) P1(-6.8,-3.6) P2(-6,-3.6) P3(-5.2,-3.6) P4(-4.4,-3.6) P5(-3.6,-3.6) P6(-2.8,-3.6) P7(-2,-3.6) P8(-1.2,-3.6) P9(-0.4,-3.6) P10(0.4,-3.6) P11(1.2,-3.6) P12(2,-3.6) P13(2.8,-3.6) P14(3.6,-3.6) P15(4.4,-3.6) P16(5.2,-3.6) P17(6,-3.6) P18(6.8,-3.6) R1(-6.8,-4.4) R2(-6,-4.4) R3(-5.2,-4.4) R4(-4.4,-4.4) R5(-3.6,-4.4) R6(-2.8,-4.4) R7(-2,-4.4) R8(-1.2,-4.4) R9(-0.4,-4.4) R10(0.4,-4.4) R11(1.2,-4.4) R12(2,-4.4) R13(2.8,-4.4) R14(3.6,-4.4) R15(4.4,-4.4) R16(5.2,-4.4) R17(6,-4.4) R18(6.8,-4.4) T1(-6.8,-5.2) T2(-6,-5.2) T3(-5.2,-5.2) T4(-4.4,-5.2) T5(-3.6,-5.2) T6(-2.8,-5.2) T7(-2,-5.2) T8(-1.2,-5.2) T9(-0.4,-5.2) T10(0.4,-5.2) T11(1.2,-5.2) T12(2,-5.2) T13(2.8,-5.2) T14(3.6,-5.2) T15(4.4,-5.2) T16(5.2,-5.2) T17(6,-5.2) T18(6.8,-5.2) U1(-6.8,-6) U2(-6,-6) U3(-5.2,-6) U4(-4.4,-6) U5(-3.6,-6) U6(-2.8,-6) U7(-2,-6) U8(-1.2,-6) U9(-0.4,-6) U10(0.4,-6) U11(1.2,-6) U12(2,-6) U13(2.8,-6) U14(3.6,-6) U15(4.4,-6) U16(5.2,-6) U17(6,-6) U18(6.8,-6) V1(-6.8,-6.8) V2(-6,-6.8) V3(-5.2,-6.8) V4(-4.4,-6.8) V5(-3.6,-6.8) V6(-2.8,-6.8) V7(-2,-6.8) V8(-1.2,-6.8) V9(-0.4,-6.8) V10(0.4,-6.8) V11(1.2,-6.8) V12(2,-6.8) V13(2.8,-6.8) V14(3.6,-6.8) V15(4.4,-6.8) V16(5.2,-6.8) V17(6,-6.8) V18(6.8,-6.8)
  silkscreen extent -8.15,-7.55 7.55,7.55, body extent -8.05,-8.05 8.05,8.05, height 0.25

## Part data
C1 C2 C3 C5 C6 C7 C28 C29 C38 C39 C40: library part CMP-0042976-1, "Cap Ceramic 3.3uF 10V X5R ±10% Pad SMD 0603 +85°C T/R", Digikey Part Number=1276-1892-1-ND, Manufacturer=Samsung, Mouser Part Number=187-CL10A335KP8NNNC, Operating Temperature Range="-55°C to +85°C", TempCo=15%, Temperature Characteristic=X5R, Tolerance_%=10%, ValueDisplayed=3.3uF
C4 C8 C9 C10 C11 C12 C13 C14 C15 C16 C17 C18 C19 C20 C21 C22 C23 C24 C25 C26 C27 C30 C31 C32 C33 C34 C35 C36 C37 C41 C42 C43 C44 C45 C46 C47 C48 C50 C51 C52 C53 C54 C55 C57 C76 C78 C124 C125 C126 C127 C131 C141 C154: library part CMP-0064970-1, "CAP, CERM, 0.1 uF, 16 V,+/- 10%, X7R, 0201", Cap_Case=0201, Manufacturer=MuRata, Supplier Part Number 1=81-GRM033Z71C104KE4D, TempCo=X7R, Tolerance_%=10%, Value1=Unknown, Value2=16V, ValueDisplayed=0.1uF
C49 C75 C82 C123 C128 C153: library part CMP-0006582-2, "CAP, CERM, 4.7 uF, 10 V, +/- 20%, X5R, 0402", Cap_Case=0402, Manufacturer=MuRata, TempCo=X5R, Tolerance_%=20%, Value1=Unknown, Value2=10V, ValueDisplayed=4.7uF
C56 C105 C117 C118 C119 C120 C121 C137 C138 C139 C140 C152 C155 C156 C157 C158 C159 C160 C161 C174: library part CMP-0096855-1, "Chip Multilayer Ceramic Capacitors for General Purpose, 0402, 0.10uF, X7R, 15%, 10%, 50V", Manufacturer=Murata, Operating Temperature Range="-55°C to +125°C", TempCo=15%, Temperature Characteristic=X7R, Tolerance_%=10%, ValueDisplayed=0.10uF
C58 C62 C84 C85 C94 C167 C168 C169: library part CMP-0122098-1, "Cap Ceramic Monolithic 47uF 25VDC 20% SMD Emboss T/R", Digikey Part Number=GRM31CR61E476ME44K-ND, Manufacturer=Murata, Mouser Part Number=81-GRM31CR61E476ME4K, Operating Temperature Range="-55°C to +85°C", TempCo=15%, Temperature Characteristic=X5R, Tolerance_%=20%, ValueDisplayed=47uF
C59 C60 C97 C101 C104 C107 C109 C111: library part CMP-0122097-1, "Chip Multilayer Ceramic Capacitors for General Purpose, 0805, 10uF, X5R, 15%, 10%, 50V", Manufacturer=Murata, Operating Temperature Range="-55°C to +85°C", TempCo=15%, Temperature Characteristic=X5R, Tolerance_%=10%, ValueDisplayed=10uF
C61 C67 C68 C69 C71 C72 C77 C80 C91 C92 C93 C95 C98 C99 C112 C113 C114 C115 C122: library part CMP-0006659-2, "CAP, CERM, 0.1 uF, 25 V, +/- 10%, X7R, 0402", Cap_Case=0402, Manufacturer=MuRata, Supplier Part Number 1=490-10698-1-ND, TempCo=X7R, Tolerance_%=10%, Value1=Unknown, Value2=25V, ValueDisplayed=0.1uF
C63 C64 C81: library part CMP-0089929-1, "2.2µF ±10% 25V Ceramic Capacitor X5R 0402 (1005 Metric)", Digikey Part Number=490-12703-1-ND, Manufacturer=Murata, Mouser Part Number=81-GRM155R61E225KE1D, Operating Temperature Range="-55°C to +85°C", TempCo=15%, Temperature Characteristic=X5R, Tolerance_%=10%, ValueDisplayed=2.2uF, Voltage=25V
C65 C66 C83 C86 C103: library part CMP-0006412-2, "CAP, CERM, 1000 pF, 50 V, +/- 5%, C0G/NP0, 0402", Cap_Case=0402, Manufacturer=MuRata, Supplier Part Number 1=490-3244-1-ND, TempCo=C0G/NP0, Tolerance_%=5%, Value1=Unknown, Value2=50V, ValueDisplayed=1000pF
C70 C130: library part CMP-0006352-2, "CAP, CERM, 0.01 uF, 25 V, +/- 10%, X7R, 0402", Cap_Case=0402, Manufacturer=MuRata, Supplier Part Number 1=490-6043-2-ND, TempCo=X7R, Tolerance_%=10%, Value1=Unknown, Value2=25V, ValueDisplayed=0.01uF
C73 C129: library part CMP-0007336-5, "CAP, CERM, 10 uF, 16 V, +/- 20%, X5R, 0603", Cap_Case=0603, Manufacturer=MuRata, Supplier Part Number 1=GRM188R61C106MAALD-ND, TempCo=X5R, Tolerance_%=20%, Value1=Unknown, Value2=16V, ValueDisplayed=10uF
C74 C87 C88 C89 C90 C100: library part CMP-0008305-2, "CAP, CERM, 22 uF, 25 V, +/- 20%, X5R, 0805", Cap_Case=0805, Manufacturer=MuRata, Supplier Part Number 1=490-10749-1-ND, TempCo=X5R, Tolerance_%=20%, Value1=Unknown, Value2=25V, ValueDisplayed=22uF
C79 C116: library part CMP-0121658-2, "Chip Multilayer Ceramic Capacitors for General Purpose, 0402, 1.0uF, X6S, 22%, 10%, 25V", Manufacturer=Murata, Operating Temperature Range="-55°C to +105°C", TempCo=22%, Temperature Characteristic=X6S, Tolerance_%=10%, ValueDisplayed=1.0uF
C96: library part CMP-0120207-1, "10 µF ±20% 10V Ceramic Capacitor X5R 0402 (1005 Metric)", Manufacturer=Murata, Operating Temperature Range="-55°C to +85°C", TempCo=15%, Temperature Characteristic=X5R, Tolerance_%=20%, ValueDisplayed=10uF
C102: library part CMP-0120205-1, "Multi-Layer Ceramic Capacitor 47pF C0G  ±5% 0402 Paper T/R", Manufacturer=Murata, Operating Temperature Range="-55°C to +125°C", TempCo=30ppm/°C, Temperature Characteristic=C0G, Tolerance_%=5%, ValueDisplayed=47pF
C132: library part CMP-0006696-2, "CAP, CERM, 6800 pF, 50 V, +/- 10%, X7R, 0402", Cap_Case=0402, Manufacturer=MuRata, Supplier Part Number 1=490-4515-1-ND, TempCo=X7R, Tolerance_%=10%, Value1=Unknown, Value2=50V, ValueDisplayed=6800pF
D2 D3 D4 D5 D6 D7 D8: library part CMP-0002894-2, "LED, Green, SMD", Color=green, Manufacturer="Wurth Elektronik", Value1=W, Value2=2V
D9 D10: library part CMP-0122246-1, "Red 624nm LED Indication - Discrete 2V 0402 (1005 Metric)", Color=Red, Digikey Part Number=732-13422-1-ND, Forward Current=20mA, Manufacturer=Wurth, Mouser Part Number=710-150040RS73220, Operating Temperature Range="-40°C to +85°C", Power_TotalModule=48mW
FB1 FB2: library part CMP-0089199-1, "120 Ohms @ 100MHz 1  Ferrite Bead 0603 (1608 Metric) 2A 40mOhm", Digikey Part Number=490-3991-1-ND, Impedance At Frequency="120Ω @ 100MHz", Manufacturer=Murata, Mouser Part Number=81-BLM18EG121SN1D, Operating Temperature Range="-55°C to +125°C", Tolerance_%=25%
FB3: library part CMP-0122093-1, "Chip Ferrite Bead, 0603, 100Ω @ 100MHz, 25%, 0.045Ω, 2A", Impedance At Frequency="100Ω @ 100MHz", Manufacturer=Murata, Operating Temperature Range="-55°C to +125℃", Test Frequency=100MHz, Tolerance_%=25%
FID1 FID2 FID3 FID4 FID5 FID6 FID7 FID8 FID9 FID10 FID12 FID13 FID14 FID15: library part CMP-0077181-1, "Fiducial mark.  There is nothing to buy or mount.", Manufacturer=N/A
J1 J2 J3: library part CMP-0055973-1, "Connector,  0.5mm, 60x2, SMT", Manufacturer=Samtec, Supplier Part Number 1=SAM8181-ND
J5: library part CMP-0088387-1, "CONN RCPT HI-SPD .5MM 60POS DL", Current_A=25A, Digikey Part Number=SAM8180-ND, Manufacturer=Samtec, Mouser Part Number=200-QSH03001LDA, Operating Temperature Range="-55°C to +125°C", Voltage_V=175V
J7: library part CMP-0121706-1, "Conn Unshrouded HDR 16 POS 2.54mm Solder ST SMT", Manufacturer=Samtec, Operating Temperature Range="-55°C to +125°C"
J8 J9: library part CMP-0054796-4, "Header, 2.54 mm, 3x1, Gold, TH", Manufacturer="Wurth Elektronik", Supplier Part Number 1=732-5316-ND
L1: library part CMP-0063291-1, "Inductor, Shielded Drum Core, Powdered Iron, 2.2 uH, 4.2 A, 0.0456 ohm, SMD", Manufacturer=Vishay-Dale, Supplier Part Number 1=541-1088-1-ND, Value1="0.0456 ohm", Value2=4.2A, ValueDisplayed=2.2uH
L2: library part CMP-0090842-1, "Power Inductor, shielded, composite, 1uH 20% tol, DCR 7.2mOhms, SRF 65MHz, Isat 4.8A, Irms 13A, AEC-Q200", Manufacturer=Coilcraft, Operating Temperature Range="to +165°C", Self Resonant Frequency=65MHz, Test Frequency=1MHz, Tolerance_%=20%
L3: library part CMP-0082609-1, "Inductor, Shielded, Metal Composite, 1.5 µH, 2.6 A, 0.06 ohm, SMD", Manufacturer=MuRata, PartNumber=DFE252012P-1R5M{}P2, Value1="0.06 ohm", Value2=2.6A, ValueDisplayed=1.5µH
Logo1: library part CMP-0074844-1
Logo2: library part CMP-0074838-1, "Texas Instrument Corporate Signature"
Logo3: library part CMP-0074847-1, "FCC_disclaimer"
Logo4: library part CMP-0074769-3, Manufacturer="Texas Instruments"
MH1 MH2 MH3 MH4: library part CMP-0078424-2, "PCB Mounting Hole, No Pad", Manufacturer=Any, PartNumber=N/A
Q2: library part CMP-0000948-2, "MOSFET, N-CH, 100 V, 0.17 A, SOT-323", Alternate Manufacturer=None, Manufacturer="Diodes Inc.", Supplier Part Number 1=BSS123W-FDICT-ND, Value1=1
Q3 Q4: library part CMP-0078819-2, "MOSFET, P-CH, -12 V, -4.3 A, SOT-23", Alternate Manufacturer=None, Manufacturer="Infineon Technologies", Value1="0.05 ohm", Value2="10 nC"
R1 R40 R49 R50 R157 R158 R180 R202 R203 R249 R260 R266 R267 R268: library part CMP-0026938-5, "RES, 4.7 k, 5%, 0.063 W, AEC-Q200 Grade 0, 0402", Manufacturer=Vishay-Dale, Power_W=63mW, Supplier Part Number 1=541-4.7KJCT-ND, TempCo="200 ppm/C", Tolerance_%=5%, Value2=0.063W, Value_Code=4k70, ValueDisplayed=4.7k
R2 R19 R20 R21 R22 R37 R41 R42 R46 R51 R54 R55 R80 R81 R82 R183 R184 R185 R205 R206 R222 R223 R224 R225 R226 R227 R228 R229 R230 R245 R246 R248 R250 R251 R252 R253 R254 R255 R256 R257 R258 R259 R281 R298 R299 R300 R301 R302 R303 R304 R305 R306 R307 R308 R309: library part CMP-0094798-1, "Res Thick Film 0402 10K Ohm 5% 0.063W(1/16W) ±100ppm/C Pad SMD T/R", Digikey Part Number=311-10KJRCT-ND, Manufacturer=YAGEO, Mouser Part Number=603-RC0402JR-0710KL, Operating Temperature Range="-55°C to +155°C", Power_W=63mW, TempCo=100ppm/°C, Tolerance_%=5%
R3 R5 R8 R9 R10 R11 R15 R18 R23 R25 R27 R28 R35 R36 R45 R52 R53 R56 R69 R73 R74 R75 R76 R77 R78 R96 R129 R132 R140 R149 R150 R151 R152 R153 R154 R155 R156 R159 R161 R162 R163 R164 R165 R166 R167 R168 R169 R170 R171 R172 R173 R174 R188 R204 R207 R208 R210 R211 R212 R213 R214 R215 R217 R231 R232 R235 R236 R237 R240 R241 R242 R243 R244 R247 R272 R273 R274 R275 R276 R277 R278 R313 R314 R315 R316: library part CMP-0002710-1, "0 Ohms Jumper Chip Resistor 0402 (1005 Metric) Automotive AEC-Q200 Thick Film", Digikey Part Number=P0.0JCT-ND, Manufacturer=Panasonic, Mouser Part Number=667-ERJ-2GE0R00X, Operating Temperature Range="-55°C to +155°C", Power=100mW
